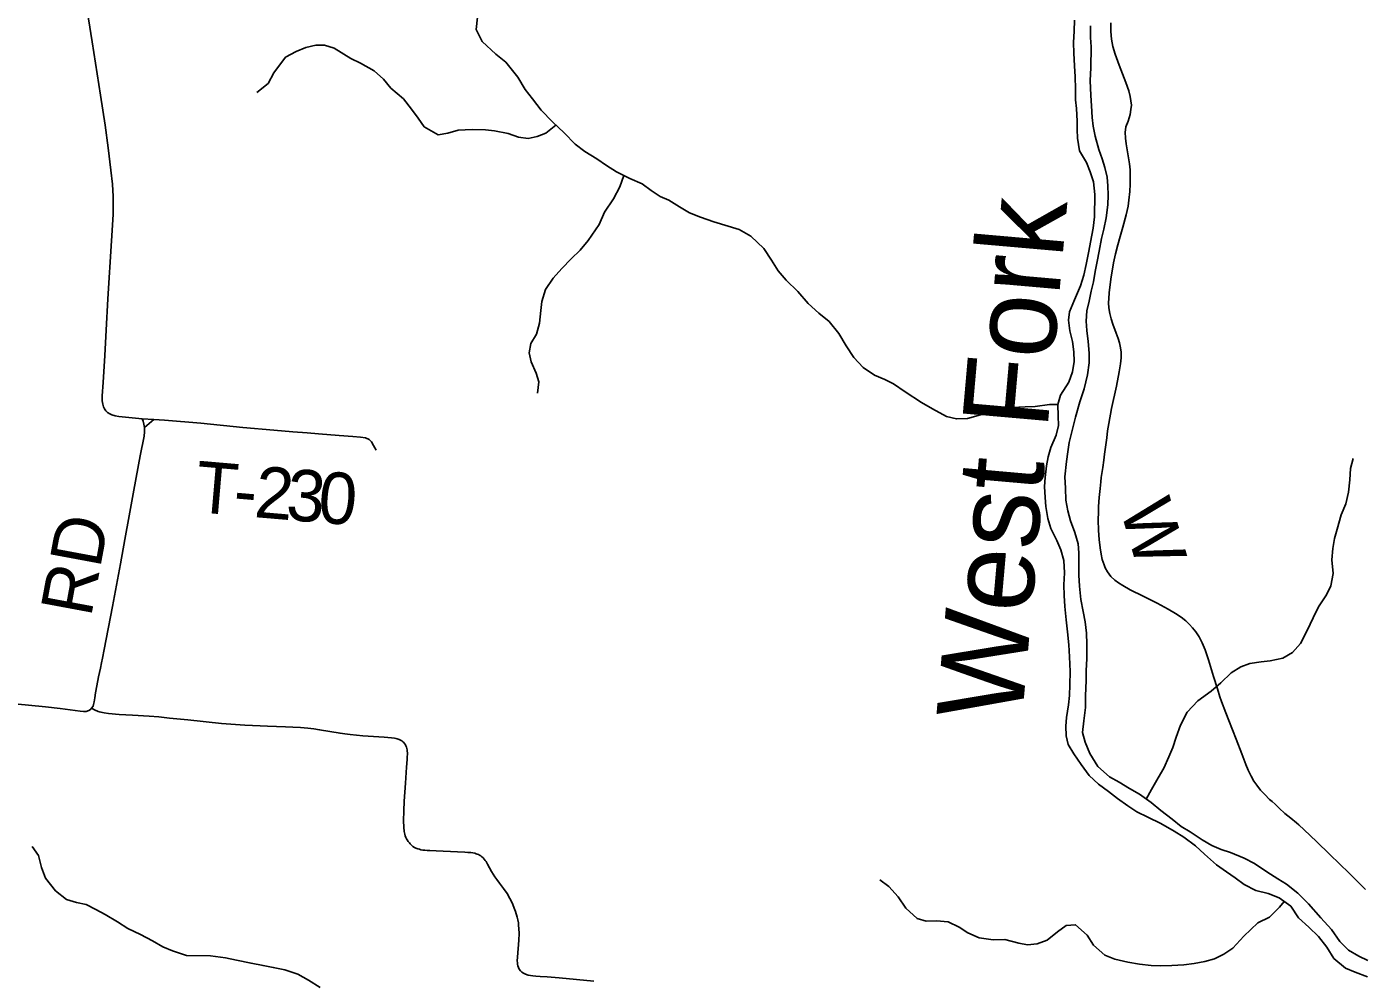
# Model space of a CAD drawing. Extents: x 1451455 to 1749751, y 218250 to 574981.
# Drawn here: x 1608144 to 1615939, y 291974 to 297536 of the extents above; entities that cross this region are included whole.
import ezdxf

# ---------------------------------------------------------------- set-up
doc = ezdxf.new("R2010")
doc.units = 0
for name, color, linetype in [('GM_X_Minor_River', 7, 'Continuous'), ('GM_X_Minor_River_Text', 7, 'Continuous'), ('GM_X_Township_Road', 7, 'Continuous'), ('GM_X_Township_Road_Text', 7, 'Continuous')]:
    doc.layers.add(name, color=color, linetype=linetype)

msp = doc.modelspace()

# ---------------------------------------------------------------- linework, layer by layer
at = {"layer": 'GM_X_Minor_River'}
for points in [[(1610772.5, 297591.1), (1610765.6, 297519.2), (1610800.7, 297450.7), (1610879.8, 297375.6), (1610939.2, 297328.8), (1611008.2, 297241.9), (1611051.3, 297169.3), (1611094.6, 297114.7), (1611143.8, 297050), (1611211, 296981.1), (1611278.2, 296916.2), (1611343.4, 296851.3), (1611398.9, 296808.5), (1611468.5, 296765.6), (1611526, 296726.8), (1611583.6, 296690), (1611661.2, 296651), (1611732.8, 296620), (1611786.4, 296581.3), (1611838, 296546.6), (1611889.7, 296523.9), (1611951.3, 296485.1), (1612008.9, 296450.3), (1612074.6, 296425.4), (1612152.3, 296398.4), (1612299.7, 296353.2)], [(1614255.4, 297574.7), (1614252.6, 297510.7), (1614249.9, 297444.7), (1614251.2, 297382.6), (1614254.3, 297308.5), (1614259.6, 297244.4), (1614260.8, 297174.4), (1614262, 297110.3), (1614267.4, 297058.2), (1614270.6, 296986.1), (1614270, 296936.1), (1614273.5, 296886), (1614284.6, 296811.9), (1614325.9, 296743.4), (1614347.3, 296689.1), (1614366.6, 296630.8), (1614373.7, 296556.7), (1614372.2, 296426.6), (1614363.5, 296360.7), (1614348.5, 296278.8), (1614337.9, 296226.9), (1614323, 296149), (1614310.3, 296087), (1614289.6, 296025.2), (1614254.6, 295943.5), (1614225.8, 295873.8), (1614221.2, 295823.8), (1614228.5, 295761.7), (1614243.8, 295699.5), (1614251.1, 295639.3), (1614252.5, 295583.3), (1614243.8, 295523.3), (1614223.1, 295463.5), (1614174.1, 295386), (1614157.5, 295332.1), (1614160.7, 295264), (1614162.1, 295209.9), (1614147.5, 295154), (1614116.6, 295082.3), (1614102, 295026.4), (1614091.4, 294974.5), (1614084.6, 294906.5), (1614080, 294854.5), (1614083.2, 294790.4), (1614088.7, 294738.3), (1614099.9, 294668.1), (1614117.2, 294609.9), (1614152.4, 294539.4), (1614175.8, 294485.1), (1614193.1, 294422.9), (1614196.3, 294350.8), (1614193.5, 294280.7), (1614194.8, 294218.6), (1614198.1, 294154.5), (1614207.2, 294076.3), (1614214.4, 294006.2), (1614221.6, 293930), (1614226.8, 293859.9), (1614229.8, 293775.8), (1614228.9, 293697.7), (1614226.2, 293635.7), (1614219.6, 293579.7), (1614208.7, 293507.7), (1614204.1, 293455.7), (1614207.5, 293399.6), (1614218.9, 293349.4), (1614250.4, 293295), (1614293.7, 293232.5), (1614341, 293167.9), (1614394.4, 293117.2), (1614454, 293074.5), (1614505.6, 293033.9), (1614567.2, 292991.2), (1614618.8, 292956.6), (1614682.5, 292925.9), (1614758.2, 292889), (1614835.7, 292844.1), (1614893.4, 292809.4), (1614960.9, 292758.6), (1615014.3, 292710), (1615083.7, 292647.1), (1615141.3, 292606.5), (1615192.9, 292571.9), (1615244.5, 292533.3), (1615312.2, 292498.5), (1615384, 292479.7), (1615449.8, 292454.9), (1615517.3, 292406.1), (1615562.6, 292337.5), (1615622, 292282.8)], [(1615754, 292269.4), (1615692.7, 292338.1), (1615619.5, 292419), (1615558.2, 292481.8), (1615492.7, 292534.6), (1615441.1, 292565.1), (1615377.5, 292605.9), (1615306, 292654.7), (1615244.3, 292685.5), (1615164.6, 292718.4), (1615110.7, 292737), (1615056.9, 292759.6), (1614999.3, 292792.2), (1614929.7, 292839.1), (1614878.1, 292871.7), (1614824.5, 292914.3), (1614759, 292965.1), (1614701.5, 293011.8), (1614634, 293058.6), (1614576.3, 293093.2), (1614516.7, 293129.9), (1614459, 293160.6), (1614391.6, 293221.4), (1614344.4, 293296), (1614317.2, 293362.4), (1614301.8, 293418.6), (1614310.6, 293486.6), (1614319.5, 293564.6), (1614320.2, 293632.6), (1614323.3, 293722.7), (1614323.9, 293778.8), (1614326.7, 293850.8), (1614327.7, 293934.9), (1614324.4, 293999), (1614317.2, 294065.1), (1614305.8, 294125.3), (1614292.6, 294195.5), (1614283.5, 294273.7), (1614280.2, 294337.8), (1614281, 294403.9), (1614279.7, 294468), (1614276.3, 294520), (1614257.1, 294586.3), (1614231.8, 294654.7), (1614216.5, 294712.9), (1614205.2, 294775.1), (1614202, 294845.2), (1614198.7, 294911.3), (1614207.7, 294999.2), (1614216.4, 295057.2), (1614225, 295111.2), (1614241.8, 295181), (1614260.8, 295258.9), (1614285.8, 295348.7), (1614310.7, 295424.5), (1614331.6, 295506.3), (1614340.5, 295576.3), (1614341.1, 295632.3), (1614335.9, 295700.5), (1614326.6, 295764.6), (1614323.2, 295818.7), (1614327.9, 295878.7), (1614340.6, 295934.6), (1614353.3, 295994.5), (1614365.9, 296048.4), (1614376.6, 296108.3), (1614387.3, 296166.3), (1614400, 296226.2), (1614412.8, 296300.1), (1614425.5, 296356), (1614440.3, 296421.9), (1614449.1, 296497.8), (1614451.8, 296553.8), (1614450.4, 296607.9), (1614445, 296658), (1614431.6, 296714.2), (1614416.2, 296766.4), (1614396.8, 296820.6), (1614375.7, 296896.9), (1614364.3, 296955.1), (1614358.9, 297007.2), (1614353.7, 297075.3), (1614350.4, 297135.4), (1614347.4, 297221.5), (1614350.2, 297295.5), (1614351.7, 297419.5), (1614348.3, 297473.6), (1614349.1, 297541.6)], [(1611230.1, 296962.6), (1611172.1, 296915.6), (1611121.8, 296896.2), (1611069.6, 296884.9), (1611011.7, 296891.7), (1610951.9, 296912.5), (1610872, 296929.6), (1610820, 296934.2), (1610742, 296937.3), (1610659.9, 296932.4), (1610599.6, 296915.2), (1610543.4, 296905.9), (1610462, 296953), (1610426.6, 297003.5), (1610389.2, 297056), (1610341.9, 297114.7), (1610268.7, 297177.7), (1610225.3, 297230.3), (1610169.9, 297279), (1610090.4, 297324.1), (1610034.7, 297350.8), (1609937.4, 297410.1), (1609881.6, 297428.9), (1609829.5, 297427.6), (1609771.3, 297414.3), (1609714.9, 297391.1), (1609652.5, 297357.9), (1609585.2, 297266.8), (1609552.4, 297205.2), (1609485.6, 297152)], [(1611626.4, 296668.5), (1611602.5, 296601.7), (1611565.5, 296532.2), (1611514.5, 296454.8), (1611483.5, 296383.2), (1611418.3, 296290), (1611371.5, 296232.6), (1611318.8, 296181.3), (1611266, 296126), (1611215.2, 296068.6), (1611170.4, 296003.2), (1611149.4, 295933.4), (1611142.8, 295881.5), (1611135.8, 295807.6), (1611116.9, 295741.8), (1611084.2, 295688.2), (1611075.5, 295634.3), (1611086.9, 295582.1), (1611116, 295515.7), (1611131.4, 295465.4), (1611122.6, 295399.5)], [(1614157.5, 295332.1), (1614109.5, 295332.6), (1614025.3, 295321.5), (1613967.2, 295318.2), (1613891.1, 295315), (1613825, 295309.7), (1613772.8, 295298.3), (1613706.5, 295273), (1613630.2, 295251.8), (1613566.1, 295248.5), (1613508.2, 295263.1), (1613426.6, 295308.1), (1613363, 295344.8), (1613267.6, 295405.9), (1613200.1, 295452.7), (1613148.4, 295479.2), (1613088.6, 295503.9), (1613023.1, 295548.7), (1612967.7, 295607.3), (1612924.4, 295673.9), (1612881.2, 295746.4), (1612824, 295817.1), (1612764.5, 295865.8), (1612701.1, 295922.5), (1612641.8, 295991.2), (1612574.5, 296058), (1612527.1, 296112.5), (1612487.8, 296175), (1612442.5, 296241.6), (1612367.3, 296314.4), (1612299.7, 296353.2)], [(1614674, 293030.8), (1614704.4, 293085.8), (1614743.2, 293155.5), (1614775.8, 293211.2), (1614804.6, 293276.9), (1614829.3, 293332.7), (1614848, 293392.6), (1614872.8, 293462.4), (1614911.7, 293538.1), (1614974.5, 293603.5), (1615053.2, 293660.7), (1615107.8, 293708.1), (1615168.5, 293767.5), (1615224.9, 293802.9), (1615277.2, 293822.4), (1615343.3, 293831.7), (1615395.5, 293837.1), (1615469.7, 293852.3), (1615526.1, 293885.7), (1615572.8, 293939.3), (1615611.7, 294014.9), (1615646.5, 294088.6), (1615679.3, 294152.3), (1615724.1, 294221.9), (1615750.7, 294275.7), (1615763.6, 294347.6), (1615756.5, 294425.8), (1615761.2, 294491.8), (1615771.9, 294551.7), (1615786.5, 294605.6), (1615811.5, 294689.4), (1615838.3, 294753.2), (1615853.1, 294821.1), (1615861.9, 294893.1), (1615864.6, 294959.1), (1615881.3, 295017)], [(1609855.2, 291931.5), (1609787.7, 291974.4), (1609726.1, 292009.3), (1609650.3, 292034.3), (1609582.4, 292049.2), (1609522.5, 292060), (1609452.6, 292073), (1609366.8, 292092.1), (1609302.9, 292105), (1609215, 292116.1), (1609076.9, 292118), (1608995.1, 292145.1), (1608937.4, 292169.9), (1608877.8, 292204.7), (1608808.2, 292241.6), (1608734.6, 292276.6), (1608673, 292315.5), (1608601.5, 292358.5), (1608547.8, 292387.2), (1608490.1, 292416), (1608434.2, 292426.8), (1608376.4, 292445.6), (1608311, 292496.5), (1608253.8, 292569.3), (1608230.6, 292631.7), (1608213.5, 292702), (1608176.1, 292754.5)], [(1615478.6, 292434.1), (1615451.2, 292400.8), (1615392.5, 292341.4), (1615324, 292308.1), (1615243.1, 292230.9), (1615178.3, 292161.5), (1615125.8, 292126.1), (1615071.5, 292098.6), (1615015.2, 292083.2), (1614953.1, 292071.9), (1614892.9, 292064.5), (1614822.8, 292059.3), (1614756.7, 292058), (1614702.7, 292060.6), (1614634.8, 292067.3), (1614566.8, 292080.1), (1614491, 292097), (1614431.2, 292119.6), (1614365.8, 292178.4), (1614328.4, 292236.9), (1614261.1, 292297.7), (1614207, 292294.3), (1614156.5, 292256.8), (1614095.9, 292207.4), (1614037.6, 292186), (1613981.5, 292180.6), (1613929.6, 292191.2), (1613849.7, 292212.1), (1613781.7, 292210.8), (1613699.7, 292221.7), (1613634, 292250.5), (1613582.3, 292283.1), (1613518.7, 292315.8), (1613450.7, 292320.6), (1613390.6, 292319.2), (1613336.7, 292333.8), (1613271.3, 292394.6), (1613226.1, 292461.2), (1613172.7, 292521.8), (1613119.1, 292560.5)], [(1615622, 292282.8), (1615677.5, 292230.2), (1615726.8, 292167.5), (1615768.1, 292101), (1615835.5, 292044.2), (1615891.3, 292021.6), (1615965, 291994.7)], [(1615966.1, 292088.8), (1615914.4, 292115.4), (1615852.7, 292150.1), (1615803.2, 292200.8), (1615754, 292269.4)]]:
    msp.add_lwpolyline(points, dxfattribs=at)
at = {"layer": 'GM_X_Township_Road'}
for points in [[(1608816.6, 295249.2), (1608681.7, 295262.9), (1608659.1, 295266.9), (1608640.1, 295272.4), (1608628.9, 295277.6), (1608615.9, 295285.8), (1608605.1, 295295.8), (1608597.2, 295307.5), (1608592.1, 295318.1), (1608587.4, 295333.8), (1608584.7, 295353.3), (1608584.6, 295382.8), (1608589.8, 295461.5), (1608600.4, 295618.5), (1608608.2, 295765.9), (1608617.9, 295949.3), (1608639.2, 296286.3), (1608648, 296440.2), (1608649.1, 296486.1), (1608648.3, 296545), (1608643.7, 296617), (1608635.5, 296698.6), (1608619.1, 296828.7), (1608600.9, 296961.9), (1608574.7, 297136.8), (1608526, 297447.5), (1608491.7, 297667.6)], [(1615952.8, 292503.8), (1615857.4, 292598.6), (1615743.7, 292707.5), (1615665.8, 292783.1), (1615594.8, 292850.9), (1615563.9, 292880.3), (1615550.1, 292893.3), (1615517.1, 292919.8), (1615499.2, 292933.3), (1615482.5, 292947.3), (1615448.8, 292978), (1615425, 293000.8), (1615407.9, 293016), (1615393.5, 293029.4), (1615365.1, 293056.7), (1615340.4, 293083), (1615318.1, 293111.3), (1615301.6, 293135.8), (1615285.2, 293164.2), (1615268.2, 293199.7), (1615254.8, 293233.1), (1615231.7, 293294.5), (1615198.1, 293379.7), (1615155.4, 293489.2), (1615137.5, 293534.9), (1615113.3, 293599.4), (1615103.8, 293627.4), (1615088.5, 293674.1), (1615066.9, 293746.4), (1615037.2, 293843.6), (1615016.6, 293902.3), (1615000.1, 293941.6), (1614982.2, 293976.6), (1614962.6, 294006.9), (1614944.3, 294030.1), (1614926.7, 294049.4), (1614905.2, 294069.7), (1614877, 294092.2), (1614844.3, 294114.1), (1614801.7, 294138.7), (1614738, 294172.7), (1614656.3, 294214.6), (1614579.7, 294252.4), (1614536.3, 294275.8), (1614511.3, 294291.5), (1614490.3, 294306.9), (1614466.6, 294329.4), (1614447, 294355.6), (1614434.9, 294378.8), (1614427.3, 294396.9), (1614417.5, 294428.2), (1614410.1, 294460.3), (1614404, 294495.8), (1614398.4, 294544.6), (1614395.2, 294596.7), (1614394.2, 294658.8), (1614394.9, 294704.6), (1614395.8, 294737.4), (1614398.8, 294789.8), (1614404, 294842), (1614408, 294881.9), (1614411.3, 294907), (1614420, 294965.4), (1614425.9, 295007.6), (1614430.5, 295043.3), (1614443, 295137.5), (1614448.6, 295179.7), (1614455.6, 295221.8), (1614472, 295308.8), (1614499.5, 295440.4), (1614516.5, 295523.9), (1614524, 295569.1), (1614527.4, 295604.9), (1614527.2, 295637.7), (1614524, 295663.6), (1614517.8, 295692.5), (1614510, 295717.5), (1614498.2, 295748.2), (1614478.5, 295800.3), (1614468.7, 295831.6), (1614461, 295863.5), (1614456, 295895.8), (1614454.3, 295925.3), (1614454.7, 295951.4), (1614457.4, 295984.2), (1614467.6, 296064.3), (1614483.6, 296158.7), (1614494.9, 296210.6), (1614508.2, 296264.4), (1614521.3, 296311.6), (1614537.4, 296367.3), (1614556.7, 296439.3), (1614567.6, 296490), (1614572.3, 296524), (1614578, 296575), (1614580.8, 296617.4), (1614580.8, 296659.9), (1614579, 296700.5), (1614575.2, 296737.3), (1614562, 296818.4), (1614556.3, 296852.4), (1614552.5, 296886.4), (1614551.6, 296920.4), (1614552.5, 296935.5), (1614555.3, 296951.5), (1614567.6, 296985.5), (1614579.9, 297023.3), (1614584.6, 297053.4), (1614586.8, 297078.5), (1614584.2, 297103.6), (1614579.3, 297129.4), (1614571.2, 297161.4), (1614554.7, 297210), (1614515.6, 297312.3), (1614492.1, 297377), (1614479.5, 297421.1), (1614471.8, 297463.1), (1614467.9, 297508.8), (1614466.5, 297558)], [(1608830.8, 295197.8), (1608827, 295217.6), (1608822.3, 295235.5), (1608816.6, 295249.2)], [(1608816.6, 295249.2), (1608885.3, 295245.1)], [(1608830.8, 295197.8), (1608885.3, 295245.1)], [(1608885.3, 295245.1), (1608948, 295241.3), (1609160.3, 295222.7), (1609405, 295199.1), (1609584.7, 295182.6), (1609695.8, 295173.1), (1609780.7, 295166.4), (1609846, 295160.8), (1609966.8, 295151.2), (1610045.3, 295146.6), (1610091, 295142.3), (1610120.1, 295137.6), (1610141.2, 295128.4), (1610154.6, 295115), (1610167.5, 295093.6), (1610181.4, 295065.4)], [(1608522.7, 293560.4), (1608530.7, 293572.8), (1608534.3, 293581.8), (1608538.1, 293597.8), (1608540.9, 293620.6), (1608544.6, 293650.1), (1608552.3, 293692), (1608563.6, 293743.1), (1608574.6, 293794.3), (1608580.9, 293826.4), (1608586.1, 293852.1), (1608596.4, 293903.6), (1608644.5, 294154.9), (1608690.7, 294403.1), (1608716.4, 294545.1), (1608741.9, 294683.8), (1608768.6, 294832.3), (1608805, 295032.4), (1608828.6, 295148.1), (1608830.6, 295173.9), (1608830.8, 295197.8)], [(1608074.2, 293586.8), (1608253.6, 293568), (1608338.3, 293558.6), (1608426.1, 293547.7), (1608455.2, 293543), (1608474.9, 293541), (1608491.3, 293542.3), (1608497.5, 293543.9), (1608509.4, 293548.9), (1608517.2, 293554.7), (1608522.7, 293560.4)], [(1611451.3, 291968.2), (1611249, 291987.6), (1611180.4, 291993.4), (1611138.3, 291995.6), (1611113, 291997.3), (1611095.3, 291999.2), (1611082.4, 292001.2), (1611068, 292004.4), (1611054, 292009.1), (1611042.2, 292014.8), (1611031.1, 292022), (1611023.1, 292029.1), (1611016.2, 292039), (1611011.7, 292048.9), (1611008.8, 292058.8), (1611007.4, 292067), (1611006.2, 292075.7), (1611005.5, 292086.8), (1611005.8, 292109.7), (1611013.6, 292207.8), (1611015.4, 292247.2), (1611014.8, 292276.6), (1611013.3, 292293.8), (1611011.4, 292309.2), (1611008.4, 292326.4), (1611004.9, 292341.3), (1610994.3, 292375.8), (1610987.6, 292394.9), (1610979, 292415.6), (1610971.1, 292434), (1610962.3, 292451.2), (1610945.9, 292479.6), (1610925.6, 292509.4), (1610901.7, 292540.6), (1610885.6, 292561.3), (1610874.2, 292577.3), (1610855.4, 292608), (1610832.5, 292650.6), (1610823.4, 292666), (1610818.4, 292673.1), (1610812.6, 292680.7), (1610805.6, 292688.3), (1610798.1, 292694.9), (1610791.7, 292699.4), (1610784.4, 292703.8), (1610778.7, 292706.8), (1610772.2, 292709.8), (1610765.1, 292712.4), (1610757.1, 292714.7), (1610746.8, 292716.7), (1610734.5, 292718.7), (1610717.5, 292720.2), (1610698.5, 292720.9), (1610655.8, 292722.7), (1610531.3, 292728.8), (1610495.3, 292730.3), (1610480.3, 292731.1), (1610465.6, 292732.5), (1610454.3, 292733.7), (1610443, 292735.6), (1610434.3, 292738), (1610425, 292741), (1610414.4, 292745.2), (1610406.3, 292749.1), (1610396.8, 292755.2), (1610387.9, 292762.5), (1610380.9, 292769.2), (1610375.7, 292775.1), (1610369.4, 292783.2), (1610363, 292792.7), (1610359.2, 292799.9), (1610355.7, 292807.3), (1610352.1, 292816.6), (1610349.4, 292825.8), (1610346, 292841.7), (1610343.1, 292867.9), (1610342.2, 292903.9), (1610343.6, 292963), (1610345.9, 293018.6), (1610352.5, 293123), (1610359.1, 293217.8), (1610362.7, 293262.3), (1610363.7, 293279), (1610364, 293290), (1610364, 293300.1), (1610363.4, 293309.6), (1610362.3, 293318.1), (1610360.3, 293326.1), (1610358.4, 293333.5), (1610355.8, 293340.7), (1610352.7, 293346.8), (1610349.2, 293352.2), (1610345.6, 293357.6), (1610341, 293363), (1610336.2, 293367.6), (1610331.4, 293371.2), (1610324.7, 293374.7), (1610316.9, 293378.4), (1610310.8, 293381), (1610303.9, 293383.2), (1610297.4, 293384.7), (1610290, 293386), (1610272.1, 293388.6), (1610229.4, 293392.2), (1610105, 293400.1), (1610029.9, 293406.9), (1609999.3, 293411), (1609971.5, 293415.2), (1609851.9, 293435.5), (1609819.4, 293440.2), (1609783.6, 293444.6), (1609741.2, 293448.7), (1609695.3, 293451.3), (1609652.8, 293453.1), (1609600.3, 293454.4), (1609547.9, 293455.6), (1609505.3, 293457.5), (1609417, 293463), (1609279.5, 293472.3), (1609083.8, 293492.6), (1608976.1, 293503.8), (1608915.5, 293510.4), (1608858.7, 293514.4), (1608760.5, 293520.3), (1608683.8, 293524.7), (1608621.7, 293530.8), (1608594.8, 293534.6), (1608585.2, 293535.9), (1608578, 293536.9), (1608568.2, 293539.3), (1608560.4, 293542.4), (1608539.5, 293552.4), (1608522.7, 293560.4)]]:
    msp.add_lwpolyline(points, dxfattribs=at)

# ---------------------------------------------------------------- texts
at = {"layer": 'GM_X_Minor_River_Text'}
msp.add_text('West Fork', height=499.81, rotation=84.99011, dxfattribs=at).set_placement((1613948, 293480.1))
at = {"layer": 'GM_X_Township_Road_Text'}
for s, rotation, p in [('T', 355.08688, (1609119.2, 294705.9)), ('2', 355.12995, (1609465.8, 294676.1)), ('3', 355.22576, (1609650.4, 294660.4)), ('0', 355.55208, (1609836.5, 294644.9)), ('-', 355.09554, (1609342.8, 294686.7)), ('W', 286.25551, (1614519, 294727.9)), ('RD', 79.43951, (1608518.5, 294086.3))]:
    msp.add_text(s, height=300, rotation=rotation, dxfattribs=at).set_placement(p)

doc.saveas('drawing.dxf')
